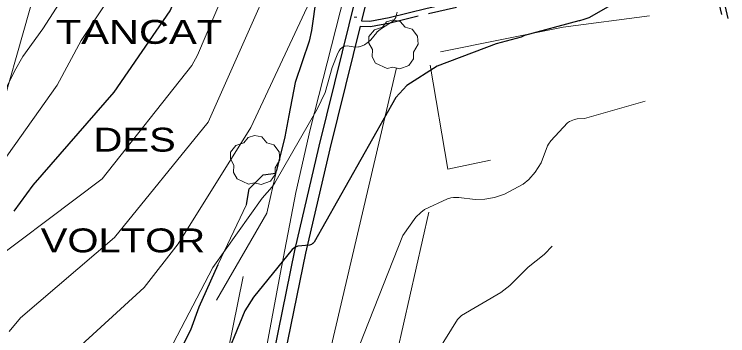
# Model space of a CAD drawing. Extents: x 480269 to 484877, y 4383588 to 4386804.
# Drawn here: x 480949.7 to 481232.9, y 4384291.8 to 4384419.5 of the extents above; entities that cross this region are included whole.
import ezdxf
from ezdxf.enums import TextEntityAlignment as Align

# ---------------------------------------------------------------- set-up
doc = ezdxf.new("R2010")
doc.units = 0
doc.header["$LTSCALE"] = 3.8
doc.linetypes.add('LONG_DASHED', pattern=[7.5, 6, -1.5])
doc.linetypes.add('MEDIUM_DASHED', pattern=[4.5, 3, -1.5])
for name, color, linetype, lineweight in [('25', 7, 'LONG_DASHED', 25), ('29', 7, 'Continuous', 13), ('38', 7, 'Continuous', 25), ('51', 7, 'Continuous', 13), ('7', 7, 'Continuous', 13), ('8', 7, 'Continuous', 25), ('9', 7, 'Continuous', 13)]:
    doc.layers.add(name, color=color, linetype=linetype, lineweight=lineweight)
doc.layers.add('5', color=7, linetype='Continuous')

msp = doc.modelspace()

# ---------------------------------------------------------------- linework, layer by layer
at = {"layer": '25'}
for points in [[(481100.37, 4384496.61), (481099.3, 4384503.33), (481096.09, 4384503.69), (481090.17, 4384504.88), (481084.77, 4384506.55), (481080.35, 4384505.2), (481077.41, 4384499.58), (481075.89, 4384489.58), (481073.51, 4384477.44), (481073.27, 4384468.82), (481071.68, 4384456.12), (481070.22, 4384447.56), (481069.95, 4384438.54), (481069.55, 4384426.58), (481067.61, 4384413.08), (481066.72, 4384408.81), (481061.19, 4384392.44), (481058.63, 4384379.23), (481057.13, 4384370.85), (481053.75, 4384357.38)], [(481041.84, 4384343.98), (481042.94, 4384350.2), (481048.42, 4384355.71), (481053.53, 4384356.37)], [(481030.44, 4384320.01), (481022.87, 4384303.12), (481019.59, 4384294.04), (481016.04, 4384287.04), (481009.92, 4384281.17), (481003.51, 4384263.01)]]:
    msp.add_lwpolyline(points, dxfattribs=at)
at = {"layer": '29'}
for points in [[(481097.66, 4384397.9), (481093.12, 4384400.02), (481091.71, 4384402.56), (481091.81, 4384405.54), (481090.44, 4384407.95), (481090.48, 4384410.7), (481092.64, 4384413.3), (481095.83, 4384414.3), (481097.48, 4384416.49), (481100.05, 4384417.32), (481102.91, 4384416.67), (481104.86, 4384414.4), (481107.67, 4384413.58), (481109.8, 4384410.73), (481110.04, 4384407.6), (481108.16, 4384404.45), (481108.16, 4384401.77), (481106.34, 4384399.16), (481102.72, 4384397.82), (481099.95, 4384398.45)], [(481042.67, 4384351.98), (481038.13, 4384354.1), (481036.72, 4384356.64), (481036.82, 4384359.62), (481035.45, 4384362.03), (481035.49, 4384364.78), (481037.65, 4384367.38), (481040.84, 4384368.38), (481042.49, 4384370.57), (481045.06, 4384371.4), (481047.92, 4384370.75), (481049.87, 4384368.48), (481052.68, 4384367.66), (481054.81, 4384364.81), (481055.05, 4384361.68), (481053.17, 4384358.53), (481053.17, 4384355.85), (481051.35, 4384353.24), (481047.73, 4384351.9), (481044.96, 4384352.53)]]:
    msp.add_lwpolyline(points, close=True, dxfattribs=at)
at = {"layer": '38'}
for points in [[(481151.17, 4384612.3), (481146.03, 4384591.73), (481140.41, 4384573.5), (481133.26, 4384558.67), (481122.94, 4384540.03), (481115.24, 4384524), (481107.55, 4384501.88), (481097.69, 4384471.66), (481087.91, 4384437.4), (481079.88, 4384404.63), (481070.58, 4384367.07), (481060.92, 4384325.61), (481052.67, 4384285.31), (481045.26, 4384245.88), (481039.17, 4384210.69), (481036.17, 4384184.48), (481035.75, 4384159.87), (481035.71, 4384143.17)], [(481131.05, 4384545.4), (481126.94, 4384537.97), (481119.4, 4384522.28), (481111.8, 4384500.44), (481101.99, 4384470.35), (481092.25, 4384436.25), (481087.51, 4384416.9)], [(481087.51, 4384416.9), (481090.87, 4384416.71), (481098.48, 4384418.19), (481113.56, 4384421.85), (481147.95, 4384429.5), (481178.78, 4384436.2), (481202.03, 4384441.02), (481214.29, 4384442.95), (481220.29, 4384442.99), (481224.42, 4384440.96), (481226.54, 4384437.66), (481229.83, 4384431.2), (481232.89, 4384417.86)], [(481087, 4384414.82), (481084.24, 4384403.56), (481074.94, 4384366.02), (481065.31, 4384324.65), (481057.08, 4384284.44), (481049.68, 4384245.09), (481043.61, 4384210.06), (481040.66, 4384184.18), (481040.24, 4384159.82), (481040.2, 4384143.16)]]:
    msp.add_lwpolyline(points, dxfattribs=at)
at = {"layer": '38', "linetype": 'MEDIUM_DASHED'}
msp.add_lwpolyline([(481087, 4384414.82), (481091.02, 4384414.6), (481098.92, 4384416.13), (481114.04, 4384419.8), (481148.41, 4384427.44), (481179.22, 4384434.14), (481202.41, 4384438.95), (481214.46, 4384440.84), (481219.81, 4384440.88), (481222.97, 4384439.33), (481224.72, 4384436.61), (481227.83, 4384430.48), (481230.83, 4384417.39)], dxfattribs=at)
at = {"layer": '51'}
for p, q in [((481070.98, 4384268.56), (481101.35, 4384398.24)), ((481030.44, 4384320.01), (481041.84, 4384343.98)), ((481114.25, 4384340.9), (481095.31, 4384257.43)), ((481040.51, 4384315.34), (481024.37, 4384235.77))]:
    msp.add_line(p, q, dxfattribs=at)
for points in [[(480967.19, 4384564.57), (480967.34, 4384552.36), (480985.69, 4384537.43), (480972.21, 4384491.15), (480963.5, 4384448.69), (480934.96, 4384348.14), (480895.4, 4384336.92), (480864.95, 4384327.79), (480840.74, 4384320.3)], [(481100.37, 4384496.61), (481089.01, 4384457.62), (481078.98, 4384420.43), (481067.18, 4384373.76), (481061.49, 4384348.77), (481055.17, 4384316.26), (481047.15, 4384272.92), (481039.18, 4384229.65), (481034.27, 4384193.67), (481031.58, 4384167.35), (481027.2, 4384144.42)], [(481118.81, 4384404.6), (481167.56, 4384414.43), (481201.89, 4384418.82)], [(481114.72, 4384399.31), (481121.77, 4384358), (481138.7, 4384361.52)], [(481053.75, 4384357.38), (481049.95, 4384340.44), (481029.91, 4384305.98)]]:
    msp.add_lwpolyline(points, dxfattribs=at)
at = {"layer": '7'}
msp.add_line((481084.65, 4384418.28), (481085.65, 4384418.28), dxfattribs=at)
at = {"layer": '8'}
for points in [[(480949.57, 4384341.32), (480957.2, 4384351.66), (480989.3, 4384388.58), (481011.58, 4384420.82), (481058.7, 4384531.96), (481087.66, 4384604.87)], [(481186.38, 4384422.91), (481177.76, 4384418.1), (481175.83, 4384417.37), (481174.02, 4384416.89), (481173.82, 4384416.85), (481152.24, 4384411.05), (481150.84, 4384410.41), (481140.97, 4384407.72), (481117.6, 4384398.89), (481105.52, 4384391.25), (481101.17, 4384386.39), (481068.71, 4384329.03), (481068.21, 4384328.51), (481068.1, 4384328.41), (481067.68, 4384328.11), (481067.2, 4384327.89), (481066.88, 4384327.79), (481062.25, 4384327.35), (481061.99, 4384327.3), (481061.22, 4384327.04), (481060.47, 4384326.51), (481059.97, 4384326.03), (481044.64, 4384307.13), (481041.19, 4384301.76), (481021.86, 4384254.56)]]:
    msp.add_lwpolyline(points, dxfattribs=at)
at = {"layer": '9'}
for points in [[(481081.21, 4384784.69), (481065.56, 4384615.68), (481054.4, 4384579.54), (480990.71, 4384431.21), (480976.24, 4384409.06), (480966.67, 4384391.32), (480939.81, 4384353.65)], [(481054.78, 4384758.44), (481040.91, 4384635.39), (481040.78, 4384624.93), (481038.28, 4384609.74), (481031.63, 4384586.97), (481028.99, 4384581.6), (481009.13, 4384540.55), (481008.69, 4384538.48), (481008.64, 4384533.7), (481008.84, 4384530.13), (481008.48, 4384527.41), (481003.8, 4384514.91), (480997.09, 4384500.91), (480976.89, 4384438.44), (480960.98, 4384413.65), (480953.01, 4384402.71), (480949.7, 4384396.94), (480942.01, 4384381.33)], [(480930.32, 4384313.39), (480984.62, 4384354.07), (481020.15, 4384399.2), (481022.38, 4384403.24), (481065.71, 4384504.92), (481103.83, 4384586.3), (481106.3, 4384589.76), (481107.19, 4384590.69), (481109.74, 4384592.74), (481121.08, 4384599.08), (481122.38, 4384600.2), (481123.63, 4384601.71), (481126.14, 4384605.91), (481133.34, 4384626.85), (481142.84, 4384681.52)], [(481067, 4384467.61), (481026.67, 4384376.63), (480989.41, 4384330.89), (480952.1, 4384298.91), (480947.67, 4384293.48)], [(480965.24, 4384277.99), (481001.19, 4384310.92), (481014.72, 4384328.37), (481043.63, 4384374.53), (481075.54, 4384443.13)], [(481011.16, 4384285.63), (481028.48, 4384318.9), (481048.12, 4384346.5), (481051.99, 4384350.91), (481053.13, 4384352.5), (481069.84, 4384381.74), (481073.05, 4384388.41), (481075.89, 4384398.38), (481078.09, 4384404.04), (481078.65, 4384405.03), (481079.18, 4384405.72), (481079.7, 4384406.22), (481080.24, 4384406.61), (481080.74, 4384406.81), (481081.07, 4384406.87), (481081.75, 4384406.89), (481084.97, 4384406.46), (481086.3, 4384406.5), (481086.61, 4384406.55), (481087.83, 4384406.95), (481088.64, 4384407.38), (481090.21, 4384408.43), (481091.22, 4384409.36), (481093.58, 4384412.27), (481093.65, 4384412.35), (481094.99, 4384413.56), (481100.21, 4384416.87), (481100.58, 4384417.3), (481100.76, 4384417.61), (481101.07, 4384418.26), (481101.32, 4384419.02), (481101.62, 4384420.27)], [(481200.1, 4384384.99), (481176.05, 4384378.11), (481173.12, 4384377.95), (481172.04, 4384377.69), (481170.09, 4384376.85), (481169.23, 4384376.32), (481162.62, 4384369.22), (481161.72, 4384367.94), (481161.33, 4384367.24), (481158.83, 4384360.54), (481156.47, 4384356.78), (481153.88, 4384353.81), (481151.67, 4384352.05), (481144.28, 4384348.06), (481140.32, 4384346.7), (481136.43, 4384346.08), (481132.69, 4384345.98), (481126.12, 4384346.74), (481124.06, 4384346.72), (481122.96, 4384346.56), (481121.71, 4384346.19), (481112.53, 4384341.92), (481111.02, 4384340.79), (481109.08, 4384338.9), (481103.92, 4384331.65), (481063.53, 4384229.27)], [(481052.72, 4384143.13), (481054.22, 4384148.44), (481105.83, 4384255.44), (481106.37, 4384257.8), (481106.37, 4384257.88), (481106.34, 4384257.87), (481106.33, 4384257.86), (481108.03, 4384267.6), (481110.02, 4384273.11), (481125.63, 4384298.28), (481127.14, 4384299.8), (481142.77, 4384309.04), (481146.37, 4384311.8), (481153.47, 4384318.96), (481153.51, 4384318.97), (481153.53, 4384318.98), (481153.58, 4384319.01), (481153.61, 4384319.05), (481153.62, 4384319.06), (481153.62, 4384319.07), (481153.63, 4384319.11), (481159.96, 4384324.09), (481160.18, 4384324.27), (481163.18, 4384327.43)]]:
    msp.add_lwpolyline(points, dxfattribs=at)

# ---------------------------------------------------------------- texts
at = {"layer": '5'}
for s, width, p in [('TANCAT ', 1.3, (481036.79, 4384407.74)), ('DES ', 1.25, (481018.18, 4384364.94)), (' VOLTOR', 1.25, (481025.45, 4384324.93))]:
    msp.add_text(s, height=9.5, dxfattribs=dict(at, width=width)).set_placement(p, align=Align.RIGHT)

doc.saveas('drawing.dxf')
